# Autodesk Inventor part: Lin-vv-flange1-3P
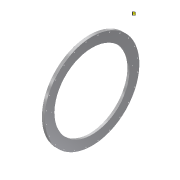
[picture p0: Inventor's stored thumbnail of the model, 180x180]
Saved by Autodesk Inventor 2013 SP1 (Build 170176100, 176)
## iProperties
Created: 2012-05
Part Number: Lin-vv-flange1-3P
Material: Stainless Steel, 304
Description: VACUUM VESSEL FLANGE
Document SubType Name: Modeling
Designer: Henneborn
Manufacturer: Standard
Standards Organization: Custom
Mass: 112129 g
Surface Area: 10360.2 cm^2
Volume: 14193.6 cm^3
Density: 7.9 g/cm^3
Rohmasse: 42,5" O.D. x 1,5" made of sheet
Author: vm
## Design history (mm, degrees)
sketch "Sketch1"
  geometry: L1 (-7.366, 0)-(44.196, 0) reference; L2 (0, -119.38)-(0, 716.28) reference; L3 (0, 596.9)-(36.83, 596.9); L4 (36.83, 596.9)-(36.83, 482.798); L5 (30.48, 473.075)-(0, 473.075); L6 (0, 473.075)-(0, 596.9); L7 (30.48, 473.075)-(30.48, 482.798); L8 (30.48, 482.798)-(36.83, 482.798); 1 further point
  constraints: 12 end point, 2 parallel, 2 perpendicular, 1 horizontal, 1 point on line
  dimensions: "d0" = 596.9 distance between parallel lines of L1 L3; "d1" = 36.83 distance between parallel lines of L4 L6; "d22" = 473.075 distance between parallel lines of L1 L5; "d23" = 482.79844 distance between parallel lines of L1 L8; "d27" = 6.35 distance between parallel lines of L4 L7
revolve "Revolution1" sketch "Sketch1" stored, may be unused: angle "d6" = 90 deg
chamfer "Chamfer2" distance "d28" = 3.81; stored, may be unused: second distance "d29" = 3.175, angle "d30" = 45 deg
chamfer "Chamfer4" distance "d62" = 1.524; stored, may be unused: second distance "d63" = 3.175, angle "d64" = 45 deg
sketch "Sketch11"
  geometry: C1 r 595.376 at (0, 0) reference; C2 r 474.599 at (0, 0) reference; 2 further points
  dimensions: "d117" = 25.4 vertical distance of C1.centre point (-508, 25.4); "d118" = 508 horizontal distance of C2.centre point (-508, 25.4); "d119" = 508 horizontal distance of C1.centre point (508, 25.4); "d120" = 25.4 vertical distance of C2.centre point (508, 25.4)
hole "Hole8" sketch "Sketch11" at (-508, 25.4), (508, 25.4) diameter "d121" = 12.6873; stored, may be unused: countersink angle "d125" = 82 deg, drill point angle "d127" = 118 deg; dims "d122" = 19.05, "d123" = 9.525, "d124" = 6.35, "d126" = 20.32
sketch "Sketch15"
  geometry: C1 r 482.798 at (0, 0) reference; 1 further point
  dimensions: "d143" = 579.12 distance of C1.centre point (75.59, 574.166)
hole "Hole10" sketch "Sketch15" at (75.59, 574.166) diameter "d145" = 15.4686; stored, may be unused: countersink angle "d149" = 82 deg, drill point angle "d151" = 118 deg; dims "d146" = 19.05, "d147" = 9.525, "d148" = 6.35, "d150" = 25.4
body "Solid1"
pattern_circular "Circular Pattern8" dims angle "d153" = 360 deg
